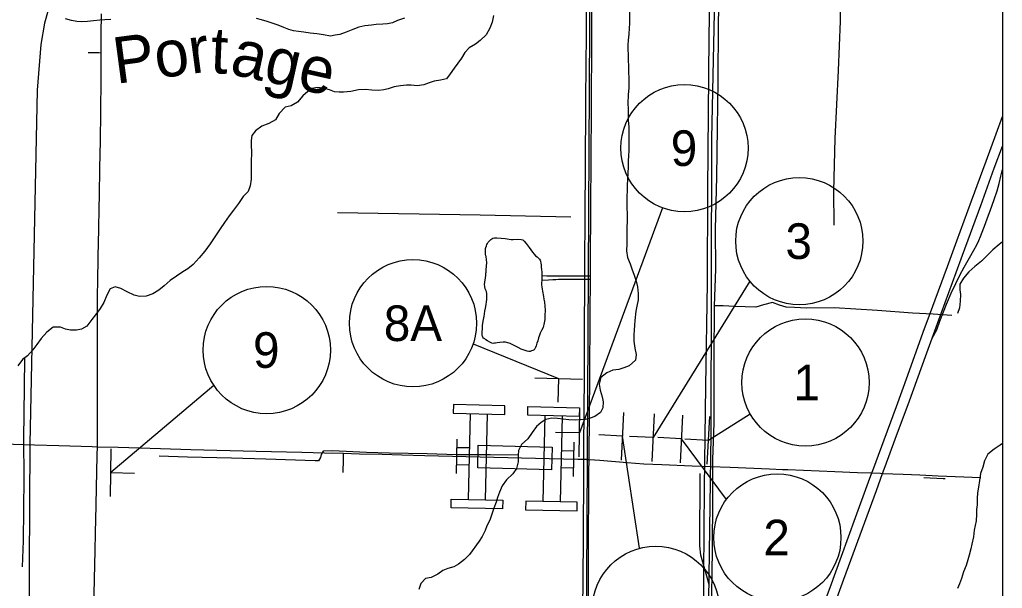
# Model space of a CAD drawing. Extents: x 0 to 680, y 0 to 834.
# Drawn here: x 297.4 to 374.7, y 104.1 to 148.8 of the extents above; entities that cross this region are included whole.
import ezdxf

# ---------------------------------------------------------------- set-up
doc = ezdxf.new("R2010")
doc.units = 0
for name, color, linetype in [('GM_X_Interchange_Ramps', 7, 'Continuous'), ('GM_X_Interstate_Route', 7, 'Continuous'), ('GM_X_Major_River', 7, 'Continuous'), ('GM_X_Major_River_Text', 7, 'Continuous'), ('GM_X_Minor_River', 7, 'Continuous'), ('GM_X_Rail_Line', 7, 'Continuous'), ('GM_X_State_Location', 7, 'Continuous'), ('GM_X_State_Route', 7, 'Continuous'), ('GM_X_Township_Road', 7, 'Continuous'), ('MT_P_Cells', 7, 'Continuous'), ('SH_Text', 7, 'Continuous')]:
    doc.layers.add(name, color=color, linetype=linetype)

msp = doc.modelspace()

# ---------------------------------------------------------------- linework, layer by layer
at = {"layer": 'GM_X_Interchange_Ramps'}
msp.add_lwpolyline([(369.181, 123.718), (369.292, 123.896), (369.441, 124.183), (369.533, 124.386), (369.791, 125.046), (370.313, 126.381), (370.681, 127.262), (371.027, 128.023), (371.343, 128.666), (371.681, 129.297), (372.1, 130.02), (372.463, 130.638), (372.688, 131.059), (372.839, 131.383), (372.975, 131.715), (373.095, 132.052), (373.357, 132.719), (373.518, 133.169), (373.723, 133.73), (374.051, 134.627), (374.274, 135.307), (374.444, 135.88), (374.587, 136.459), (374.693, 136.966)], dxfattribs=at)
at = {"layer": 'GM_X_Interstate_Route'}
msp.add_lwpolyline([(44.693, 394.069), (374.693, 394.069), (374.693, 64.069), (44.693, 64.069)], close=True, dxfattribs=at)
for points in [[(360.405, 102.107), (361.146, 104.124), (362.049, 106.59), (363.163, 109.614), (364.174, 112.422), (364.438, 113.125), (364.51, 113.316), (365.675, 116.448), (366.363, 118.358), (367.274, 120.821), (368.482, 124.192), (368.978, 125.535), (370.394, 129.339), (371.124, 131.36), (372.269, 134.5), (373.412, 137.641), (374.197, 139.769), (374.693, 141.129)], [(361.509, 102.772), (362.246, 104.79), (364.79, 111.74), (365.284, 113.091), (365.487, 113.645), (366.257, 115.778), (367.385, 118.797), (368.655, 122.273), (369.181, 123.718), (369.921, 125.75), (371.074, 128.887), (371.565, 130.232), (372.994, 134.158), (374.052, 137.075), (374.693, 138.815)]]:
    msp.add_lwpolyline(points, dxfattribs=at)
at = {"layer": 'GM_X_Major_River'}
for points in [[(302.769, 148.613), (302.346, 148.585), (301.953, 148.615), (301.516, 148.689), (301.065, 148.807)], [(304.605, 148.768), (304.138, 148.74), (303.76, 148.712), (303.249, 148.655), (302.769, 148.613)], [(327.697, 148.875), (327.143, 148.687), (326.749, 148.513), (326.37, 148.427), (325.991, 148.399), (325.481, 148.357), (325.116, 148.328), (324.577, 148.257), (324.111, 148.156), (323.629, 147.983), (323.119, 147.765), (322.623, 147.592), (322.244, 147.52), (321.879, 147.463), (321.326, 147.552), (320.802, 147.641), (320.278, 147.701), (319.797, 147.775), (319.36, 147.82), (318.967, 147.865), (318.603, 147.968), (318.21, 148.13), (317.759, 148.321), (317.308, 148.482), (316.9, 148.615), (316.449, 148.733), (316.056, 148.836)]]:
    msp.add_lwpolyline(points, dxfattribs=at)
at = {"layer": 'GM_X_Minor_River'}
for points in [[(362.295, 170.306), (362.241, 167.81), (362.262, 165.053), (362.281, 162.019), (362.103, 160.867), (362.128, 159.54), (362.192, 156.695), (362.155, 154.303), (362.058, 151.211), (361.953, 150.19), (361.934, 148.63), (361.776, 144.765), (361.527, 139.412), (361.412, 135.284), (361.448, 132.599)], [(351.702, 152.087), (351.629, 147.405), (351.52, 135.385), (351.483, 128.033), (351.356, 119.966), (351.26, 111.987), (351.21, 105.174), (351.169, 101.104), (351.114, 92.789), (351.127, 87.435), (351.104, 84.488), (351.101, 78.551), (351.032, 75.196), (350.922, 67.479), (350.857, 64.069)], [(352.398, 150.962), (352.346, 148.366), (352.318, 143.917), (352.278, 140.255), (352.237, 136.39), (352.122, 132.276), (352.142, 129.14), (352.046, 126.252), (352.004, 122.065), (352.003, 117.047), (351.907, 114.173), (351.898, 111.153), (351.871, 107.113), (351.831, 103.524), (351.79, 99.337), (351.749, 95.457), (351.733, 90.074), (351.75, 86.12)], [(345.387, 149.874), (345.382, 148.444), (345.352, 148.08), (345.336, 147.613), (345.291, 147.146), (345.261, 146.782), (345.26, 146.403), (345.273, 145.994), (345.286, 145.6), (345.299, 145.06), (345.312, 144.608), (345.326, 144.17), (345.324, 143.777), (345.338, 143.354), (345.292, 142.872), (345.261, 142.143), (345.274, 141.764), (345.273, 141.384), (345.286, 140.845), (345.328, 140.305), (345.341, 139.75), (345.339, 138.963), (345.323, 138.467), (345.307, 138.044), (345.291, 137.65), (345.275, 137.169), (345.259, 136.716), (345.228, 136.162), (345.198, 135.768), (345.196, 135.287), (345.181, 134.879), (345.178, 133.974), (345.205, 133.493), (345.189, 132.938), (345.173, 132.399), (345.172, 131.976), (345.185, 131.523), (345.169, 131.144), (345.153, 130.59), (345.239, 130.05), (345.427, 129.553), (345.571, 129.174), (345.759, 128.677), (345.918, 128.21), (346.019, 127.757), (346.061, 127.232), (346.059, 126.736), (345.97, 126.226), (345.896, 125.847), (345.807, 125.117), (345.776, 124.753), (345.761, 124.359), (345.73, 123.994), (345.714, 123.484), (345.815, 122.944), (345.9, 122.433), (345.87, 121.995), (345.359, 121.545), (344.936, 121.385), (344.557, 121.27), (344.076, 121.198), (343.609, 120.995), (343.141, 120.632), (342.994, 120.107), (343.08, 119.64), (343.224, 119.115), (343.31, 118.706), (343.294, 118.254), (343.104, 117.89), (342.666, 117.555), (342.287, 117.425), (341.908, 117.339), (341.485, 117.296), (341.121, 117.268), (340.611, 117.299), (340.174, 117.358), (339.722, 117.403), (339.285, 117.434), (338.819, 117.333)], [(334.705, 149.074), (334.587, 148.563), (334.411, 148.082), (334.118, 147.558), (333.65, 147.107), (333.271, 146.831), (332.789, 146.541), (332.438, 146.163), (332.174, 145.711), (331.896, 145.318), (331.604, 144.94), (331.296, 144.488), (331.004, 144.096), (330.537, 143.995), (330.042, 143.909), (329.633, 143.779), (329.225, 143.619), (328.7, 143.548), (328.22, 143.608), (327.855, 143.609), (327.374, 143.552), (326.879, 143.466), (326.427, 143.321), (326.062, 143.235), (325.669, 143.177), (325.13, 143.208), (324.635, 143.268), (324.081, 143.226), (323.469, 143.096), (322.915, 143.054), (322.551, 143.041), (322.186, 143.085), (321.808, 143.232), (321.328, 143.365), (320.847, 143.425), (320.454, 143.339), (320.089, 143.106), (319.709, 142.757), (319.299, 142.277), (318.803, 141.987), (318.322, 141.871), (317.84, 141.377), (317.547, 140.882), (317.036, 140.577), (316.496, 140.374), (315.985, 140.026), (315.693, 139.647), (315.648, 139.253), (315.647, 138.874), (315.66, 138.349), (315.657, 137.547), (315.641, 137.167), (315.654, 136.671), (315.653, 136.219), (315.564, 135.68), (315.402, 135.243), (315.022, 134.85), (314.642, 134.297), (314.247, 133.787), (313.911, 133.321), (313.545, 132.797), (313.208, 132.317), (312.784, 131.676), (312.418, 131.123), (312.008, 130.57), (311.569, 130.046), (311.087, 129.508), (310.664, 129.159), (310.269, 128.926), (309.773, 128.592), (309.291, 128.244), (308.795, 127.822), (308.386, 127.502), (307.919, 127.212), (307.394, 127.024), (306.869, 126.982), (306.447, 127.1), (305.909, 127.364), (305.414, 127.613), (304.963, 127.746), (304.569, 127.601), (304.305, 127.106), (304.056, 126.523), (303.778, 126.057), (303.412, 125.562), (303.119, 125.184), (302.725, 124.674), (302.316, 124.428), (301.922, 124.341), (301.456, 124.343), (301.048, 124.431), (300.655, 124.578), (300.087, 124.58), (299.576, 124.188), (299.138, 123.693), (298.786, 123.213), (298.494, 122.805), (298.055, 122.34), (297.661, 122.034)], [(340.776, 133.228), (333.637, 133.38), (322.42, 133.559)], [(374.693, 131.296), (374.453, 131.074), (373.957, 130.652), (373.518, 130.23), (373.065, 129.765), (372.539, 129.343), (372.057, 128.922), (371.648, 128.441), (371.341, 127.976), (371.354, 127.523), (371.396, 127.158), (371.366, 126.619), (371.335, 126.108), (371.173, 125.657)], [(370.721, 125.512), (369.25, 125.604), (367.633, 125.696), (364.88, 125.894), (361.486, 126.108), (359.301, 126.085), (358.368, 126.117), (357.698, 126.148), (357.189, 126.324), (356.621, 126.516), (355.921, 126.328), (355.319, 126.154), (353.648, 126.218), (352.742, 126.248), (352.046, 126.252)], [(297.836, 122.17), (297.8, 119.831), (297.744, 115.805), (297.779, 112.727), (297.735, 107.796), (297.641, 105.754)], [(297.661, 122.034), (297.295, 121.539)], [(338.819, 117.333), (338.454, 117.101), (338.074, 116.781), (337.738, 116.315), (337.401, 115.82), (336.89, 115.355), (336.67, 114.903), (336.625, 114.524), (336.638, 113.999), (336.505, 113.474), (336.213, 113.066), (335.73, 112.586), (335.379, 112.12), (335.159, 111.625), (335.012, 111.202), (334.895, 110.838), (334.733, 110.372), (334.557, 109.891), (334.41, 109.41), (334.175, 108.973), (334.028, 108.594), (333.809, 108.142), (333.56, 107.764), (332.799, 106.716), (332.404, 106.323), (331.952, 105.96), (331.572, 105.756), (331.106, 105.612), (330.712, 105.467), (330.317, 105.177), (329.807, 104.915), (329.355, 104.829), (328.99, 104.451), (328.828, 103.97)], [(374.693, 115.433), (374.522, 115.318), (374.055, 114.984), (373.559, 114.606), (373.28, 114.082), (373.162, 113.586), (372.986, 113.091), (372.897, 112.522), (372.808, 112.012), (372.733, 111.574), (372.718, 111.122), (372.716, 110.626), (372.671, 110.262), (372.655, 109.853), (372.625, 109.372), (372.551, 109.007), (372.477, 108.628), (372.417, 108.118), (372.299, 107.52), (372.21, 107.156), (372.078, 106.675), (371.975, 106.31), (371.842, 105.844), (371.637, 105.348), (371.475, 104.824), (371.313, 104.416), (371.181, 104.051)], [(336.625, 114.524), (334.44, 114.545), (331.774, 114.553), (329.486, 114.618), (326.529, 114.685), (324.708, 114.748), (322.028, 114.858), (321.299, 114.831), (321.153, 114.584), (321.094, 114.336), (320.933, 114.088), (320.671, 114.089), (316.795, 114.202), (314.1, 114.283), (310.633, 114.381), (308.404, 114.46)]]:
    msp.add_lwpolyline(points, dxfattribs=at)
at = {"layer": 'GM_X_Rail_Line'}
for points in [[(351.218, 64.069), (351.448, 90.121), (351.798, 116.184), (351.86, 139.423), (352.175, 154.252), (352.451, 189.912), (352.901, 229.863), (353.003, 247.107), (353.355, 298.069), (353.602, 311.675), (353.78, 316.856), (353.954, 319.076), (354.473, 323.516), (355.976, 338.772), (356.265, 341.847), (356.561, 344.985), (356.644, 347.076), (356.685, 349.146), (356.788, 357.395), (356.901, 372.817), (357.146, 391.252), (357.174, 394.069)], [(341.694, 64.069), (341.887, 75.733), (342.297, 152.995), (342.913, 209.384), (343.255, 230.188), (343.597, 251.334), (344.253, 291.298), (344.078, 319.736), (344.92, 358.256)], [(324.019, 224.102), (323.747, 191.887), (316.336, 170.579), (315.011, 167.69), (314.008, 166.083), (312.961, 164.64), (304.58, 156.45), (302.834, 154.704), (301.197, 152.565), (299.926, 150.355), (299.392, 148.48), (299.125, 146.806), (298.837, 143.215), (298.255, 115.425), (298.139, 96.174), (297.69, 68.538), (297.562, 64.069)], [(351.639, 104.348), (351.477, 105.024), (351.203, 105.928), (350.987, 106.665), (350.913, 107.411), (350.949, 113.082)]]:
    msp.add_lwpolyline(points, dxfattribs=at)
at = {"layer": 'GM_X_State_Route'}
msp.add_line((341.999, 114.198), (342.202, 114.187), dxfattribs=at)
for points in [[(342.174, 103.184), (342.15, 104.975), (342.158, 107.004), (342.17, 108.795), (342.19, 110.943), (342.193, 113.211), (342.202, 114.187), (342.235, 117.867), (342.256, 120.613), (342.303, 125.745), (342.32, 128.356), (342.321, 128.607), (342.326, 129.327), (342.329, 131.236), (342.335, 132.431), (342.351, 133.982), (342.375, 137.802), (342.398, 141.741), (342.418, 147.352), (342.434, 150.814)], [(341.721, 103.016), (341.74, 104.208), (341.769, 108.624), (341.791, 112.682), (341.802, 114.206), (341.808, 114.95), (341.819, 118.172), (341.837, 120.559), (341.838, 123.066), (341.854, 124.856), (341.862, 127.602), (341.867, 128.355), (341.869, 128.607), (341.871, 128.914), (341.908, 133.927), (341.927, 136.791), (341.963, 142.521), (341.998, 147.653), (342.01, 149.682)], [(296.12, 115.41), (298.625, 115.334), (300.534, 115.282), (303.158, 115.199), (303.559, 115.188), (305.186, 115.142), (306.856, 115.099), (308.527, 115.053), (310.912, 114.981), (316.042, 114.838), (319.622, 114.754), (321.411, 114.709), (322.915, 114.671), (324.155, 114.639), (325.945, 114.598), (327.496, 114.555), (329.286, 114.51), (339.069, 114.271), (341.336, 114.209), (341.802, 114.206), (341.975, 114.2), (341.999, 114.198)], [(342.202, 114.187), (343.052, 114.124), (345.193, 113.945), (346.503, 113.854), (347.934, 113.782), (350.32, 113.694), (351.751, 113.638), (353.301, 113.574), (356.402, 113.45), (357.419, 113.408)], [(357.419, 113.408), (357.833, 113.391), (361.529, 113.241), (363.318, 113.169), (364.438, 113.125), (365.107, 113.099), (365.284, 113.091), (366.896, 113.026), (368.208, 112.977), (369.638, 112.914), (371.664, 112.828), (372.976, 112.774), (373.014, 112.772)], [(368.523, 112.772), (370.036, 112.703), (370.202, 112.696)]]:
    msp.add_lwpolyline(points, dxfattribs=at)
at = {"layer": 'GM_X_Township_Road'}
for p, q in [((338.488, 128.655), (338.482, 128.283)), ((341.867, 128.355), (342.082, 128.355)), ((341.869, 128.607), (342.083, 128.607))]:
    msp.add_line(p, q, dxfattribs=at)
for points in [[(303.859, 146.153), (303.865, 147.81), (303.876, 149.003), (303.878, 149.202)], [(302.829, 146.178), (303.178, 146.169), (303.683, 146.157), (303.859, 146.153)], [(303.559, 115.188), (303.561, 115.468), (303.57, 120.004), (303.573, 121.555), (303.572, 122.51), (303.572, 123.344), (303.565, 124.896), (303.576, 127.165), (303.596, 128.119), (303.625, 130.148), (303.676, 132.296), (303.706, 133.967), (303.727, 134.921), (303.763, 137.069), (303.795, 139.217), (303.827, 141.484), (303.845, 144.11), (303.859, 146.153)], [(338.482, 128.283), (338.479, 128.06), (338.478, 127.918), (338.487, 127.753), (338.512, 127.576), (338.549, 127.403), (338.637, 126.99), (338.664, 126.795), (338.695, 126.548), (338.744, 125.929), (338.739, 125.512), (338.725, 125.176), (338.678, 124.92), (338.593, 124.569), (338.478, 124.315), (338.375, 124.114), (338.276, 123.868), (338.241, 123.755), (338.167, 123.517), (338.112, 123.332), (338.049, 123.115), (338.001, 122.987), (337.955, 122.881), (337.923, 122.844), (337.886, 122.815), (337.845, 122.788), (337.782, 122.748), (337.691, 122.712), (337.589, 122.678), (337.461, 122.669), (337.334, 122.689), (337.182, 122.745), (337.016, 122.801), (336.869, 122.868), (336.647, 122.981), (336.476, 123.076), (336.154, 123.232), (336.07, 123.274), (335.993, 123.308), (335.917, 123.331), (335.813, 123.36), (335.637, 123.393), (335.453, 123.412), (335.187, 123.383), (334.974, 123.359), (334.865, 123.336), (334.771, 123.321), (334.671, 123.312), (334.572, 123.331), (334.41, 123.411), (334.23, 123.511), (334.102, 123.601), (334.003, 123.667), (333.917, 123.729), (333.861, 123.8), (333.828, 123.866), (333.808, 123.923), (333.799, 123.984), (333.794, 124.06), (333.794, 124.221), (333.823, 124.458), (333.838, 124.693), (333.837, 124.75), (333.898, 125.178), (333.95, 125.415), (333.992, 125.633), (334.026, 125.841), (334.068, 126.083), (334.115, 126.372), (334.144, 126.571), (334.158, 126.765), (334.177, 126.922), (334.172, 127.035), (334.172, 127.215), (334.138, 127.391), (334.093, 127.499), (334.053, 127.594), (334.01, 127.779), (333.986, 127.95), (334.083, 128.643), (334.098, 128.821), (334.108, 128.904), (334.116, 128.977), (334.117, 129.028), (334.119, 129.101), (334.161, 129.674), (334.142, 129.864), (334.114, 130.13), (334.1, 130.194), (334.076, 130.333), (334.066, 130.451), (334.066, 130.579), (334.066, 130.64), (334.075, 130.768), (334.094, 130.856), (334.137, 130.963), (334.183, 131.077), (334.222, 131.152), (334.28, 131.255), (334.397, 131.403), (334.483, 131.474), (334.563, 131.531), (334.655, 131.569), (334.762, 131.593), (334.956, 131.617), (335.302, 131.588), (335.615, 131.546), (335.769, 131.516), (335.934, 131.492), (336.079, 131.48), (336.254, 131.482), (336.591, 131.509), (336.865, 131.485), (336.989, 131.447), (337.06, 131.404), (337.116, 131.352), (337.26, 131.17), (337.409, 130.96), (337.494, 130.832), (337.75, 130.476), (337.88, 130.325), (338.003, 130.197), (338.117, 130.105), (338.231, 130.012), (338.306, 129.927), (338.358, 129.837), (338.378, 129.771), (338.403, 129.626), (338.43, 129.477), (338.449, 129.297), (338.472, 129.117), (338.492, 128.894), (338.488, 128.655)], [(338.482, 128.283), (339.022, 128.312), (339.354, 128.324), (339.591, 128.341), (339.808, 128.349), (340.661, 128.351), (341.867, 128.355)], [(338.488, 128.655), (338.894, 128.62), (339.529, 128.611), (339.823, 128.615), (340.724, 128.613), (341.341, 128.606), (341.869, 128.607)], [(342.082, 128.355), (342.171, 128.356), (342.32, 128.356)], [(342.083, 128.607), (342.177, 128.607), (342.321, 128.607)], [(302.797, 76.737), (302.804, 77.403), (302.84, 78.954), (302.87, 80.266), (302.919, 82.773), (302.955, 84.443), (303, 86.83), (303.048, 89.217), (303.101, 91.842), (303.145, 94.707), (303.18, 96.138), (303.19, 97.212), (303.217, 99.122), (303.253, 101.271), (303.356, 105.925), (303.389, 106.998), (303.422, 108.43), (303.467, 110.577), (303.498, 112.008), (303.526, 113.201), (303.554, 114.514), (303.559, 115.188)], [(322.878, 113.164), (322.904, 114.198), (322.912, 114.557), (322.915, 114.671)]]:
    msp.add_lwpolyline(points, dxfattribs=at)
at = {"layer": 'MT_P_Cells'}
for p, q in [((332.724, 111.041), (332.884, 117.789)), ((334.073, 111.009), (334.233, 117.757)), ((338.736, 117.631), (338.576, 110.883)), ((340.085, 117.599), (339.925, 110.851)), ((331.823, 115.788), (331.759, 113.089)), ((332.82, 115.089), (331.807, 115.113)), ((340.986, 112.851), (341.049, 115.551)), ((333.478, 114.399), (333.478, 114.399)), ((340.021, 114.9), (341.033, 114.876)), ((332.788, 113.74), (331.775, 113.764)), ((339.33, 114.241), (339.33, 114.241)), ((339.989, 113.55), (341.001, 113.526))]:
    msp.add_line(p, q, dxfattribs=at)
for points in [[(335.599, 118.4), (331.55, 118.495), (331.534, 117.821), (335.583, 117.725)], [(337.402, 118.338), (341.451, 118.242), (341.435, 117.567), (337.386, 117.663)], [(335.407, 110.302), (331.358, 110.398), (331.374, 111.073), (335.423, 110.977)], [(337.21, 110.24), (341.259, 110.144), (341.275, 110.819), (337.226, 110.915)]]:
    msp.add_lwpolyline(points, close=True, dxfattribs=at)
at = {"layer": 'SH_Text'}
for p, q in [((347.977, 133.961), (341.453, 116.272)), ((354.851, 128.194), (347.253, 115.924)), ((333.099, 123.278), (339.81, 120.554)), ((337.935, 120.601), (341.685, 120.506)), ((339.81, 120.554), (339.763, 118.679)), ((312.712, 120.011), (304.61, 113.155)), ((341.43, 114.396), (341.477, 118.148)), ((344.751, 114.144), (344.945, 117.891)), ((347.155, 114.032), (347.349, 117.779)), ((349.387, 113.935), (349.581, 117.682)), ((351.5, 113.813), (351.694, 117.56)), ((354.881, 117.745), (351.597, 115.686)), ((341.453, 116.272), (339.577, 116.296)), ((344.848, 116.017), (342.975, 116.114)), ((346.17, 107.205), (344.848, 116.017)), ((347.252, 115.906), (345.379, 116.003)), ((349.484, 115.808), (347.611, 115.905)), ((353.003, 111.045), (349.484, 115.808)), ((351.597, 115.686), (349.723, 115.783)), ((304.578, 111.279), (304.641, 115.031)), ((304.61, 113.155), (306.486, 113.123))]:
    msp.add_line(p, q, dxfattribs=at)
msp.add_lwpolyline([(333.502, 115.3), (339.308, 115.148), (339.261, 113.37), (333.456, 113.522)], close=True, dxfattribs=at)
for centre in [(349.707, 138.652), (358.733, 131.345), (328.367, 124.893), (316.871, 122.786), (359.216, 120.235), (357.009, 108.052), (347.452, 102.372)]:
    msp.add_circle(centre, 5, dxfattribs=at)

# ---------------------------------------------------------------- texts
at = {"layer": 'GM_X_Major_River_Text'}
for s, height, rotation, p in [('Por', 3.6381, 7.58162, (305.037, 143.702)), ('t', 3.638, 357.58113, (312.414, 144.549)), ('age', 3.6381, 347.58047, (313.872, 144.505))]:
    msp.add_text(s, height=height, rotation=rotation, dxfattribs=at).set_placement(p)
at = {"layer": 'GM_X_State_Location'}
msp.add_text('281', height=0.00727, rotation=0.00001, dxfattribs=at).set_placement((333.021, 112.967))
for s in ['s', 'r']:
    msp.add_text(s, height=0.00727, dxfattribs=at).set_placement((335.588, 113.497))
at = {"layer": 'SH_Text'}
for s, p in [('9', (348.629, 137.252)), ('3', (357.644, 129.945)), ('8A', (326.073, 123.493)), ('9', (315.793, 121.386)), ('1', (358.279, 118.835)), ('2', (355.909, 106.652))]:
    msp.add_text(s, height=2.8, dxfattribs=at).set_placement(p)

doc.saveas('drawing.dxf')
